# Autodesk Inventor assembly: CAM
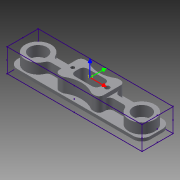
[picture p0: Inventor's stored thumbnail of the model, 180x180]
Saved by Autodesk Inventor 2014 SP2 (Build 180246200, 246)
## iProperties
Created: 2005-05
Part Number: CAM
Document SubType Name: Assembly
Designer: Administrator
Mass: 43.9253 g
Surface Area: 202.838 cm^2
Volume: 43.9253 cm^3
Density: 1 g/cm^3
Author: Administrator
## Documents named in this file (3)
- Z:\VDW-Nachwuchsstiftung Intern\Mitarbeiter Ablage\Steffen Krauth\IVCAM\KnowledgeBase Daten\SEITENTEIL1\SEITENTEIL1.IAM
- Z:\VDW-Nachwuchsstiftung Intern\Mitarbeiter Ablage\Steffen Krauth\IVCAM\KnowledgeBase Daten\SEITENTEIL1\DesignModel.ipt
- Z:\VDW-Nachwuchsstiftung Intern\Mitarbeiter Ablage\Steffen Krauth\IVCAM\KnowledgeBase Daten\SEITENTEIL1\CAM.IPT
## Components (2 placed, 2 different names)
1. DesignModel:1
2. CAM:1
